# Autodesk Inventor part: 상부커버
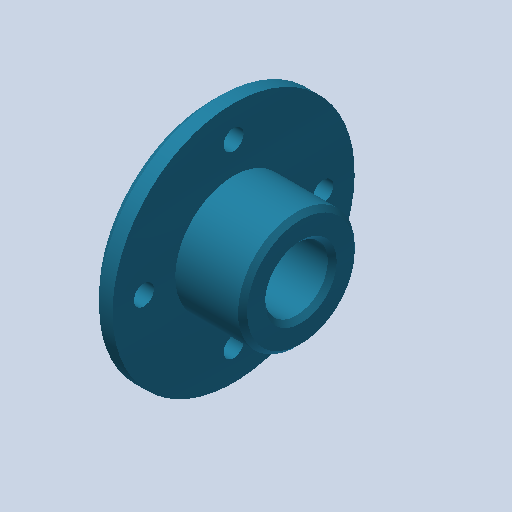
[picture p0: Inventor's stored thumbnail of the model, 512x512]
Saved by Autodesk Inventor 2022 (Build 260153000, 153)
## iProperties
Created: 2015-09
Part Number: 상부커버
Material: 알루미늄 6061
Document SubType Name: Modeling
Designer: mduedu
Density: 1 g/cm^3
Appearance: 터키옥색
Author: mduedu
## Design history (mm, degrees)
sketch "스케치1"
  geometry: L1 (-10, 0)-(10, 0); L2 (-10, 0)-(-10, 27); L3 (-10, 27)-(-5, 27); L4 (-5, 27)-(-5, 13); L5 (-5, 13)-(10, 13); L6 (10, 13)-(10, 0); 2 further points
  constraints: 12 end point, 2 parallel, 2 perpendicular, 1 coincident, 1 horizontal, 1 midpoint, 1 vertical
  dimensions: "d0" = 20 distance of L1.start L1.end; "d2" = 5 distance of L2.end L3.end; "d3" = 26 diameter of L5 L1; "d4" = 54 diameter of L3 L1
revolve "회전1" sketch "스케치1" stored, may be unused: angle "d5" = 90 deg
hole "구멍1" diameter "d8" = 14; stored, may be unused: countersink angle "d12" = 90 deg, drill point angle "d14" = 118 deg; dims "d6" = 10, "d7" = 10, "d9" = 6, "d10" = 4, "d11" = 2, "d13" = 8
chamfer "모따기1" distance "d15" = 1; stored, may be unused: second distance "d16" = 2, angle "d17" = 45 deg
chamfer "모따기2" distance "d18" = 2; stored, may be unused: second distance "d19" = 2, angle "d20" = 45 deg
sketch "스케치2" dims "d21" = 40
  geometry: 6 further points
  constraints: 2 vertical alignment, 1 coincident, 7 other
  dimensions: "d25" = 360 deg dimension on point (0, 0) point (0, 20) (derived)
sketch "스케치3"
  geometry: 4 further points
hole "구멍2" sketch "스케치3" at (0, 20), (-20, 0), (20, 0), (0, -20) diameter "d27" = 4.5; stored, may be unused: countersink angle "d31" = 90 deg, drill point angle "d33" = 0 deg; dims "d28" = 6, "d29" = 4, "d30" = 2, "d32" = 8
node "솔리드1"
